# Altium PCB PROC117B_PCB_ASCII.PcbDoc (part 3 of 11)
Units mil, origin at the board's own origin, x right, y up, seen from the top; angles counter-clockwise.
Board outline 2480.32 x 3185.25 mil, 8 copper layers (Top Layer, L2_GND1, L3_SIG1, L4_PWR1, L5_PWR2, L6_SIG2, L7_GND2, Bottom Layer), stack 57.4 mil thick; 456 components, 292 nets, 7831 pads, 2905 vias.
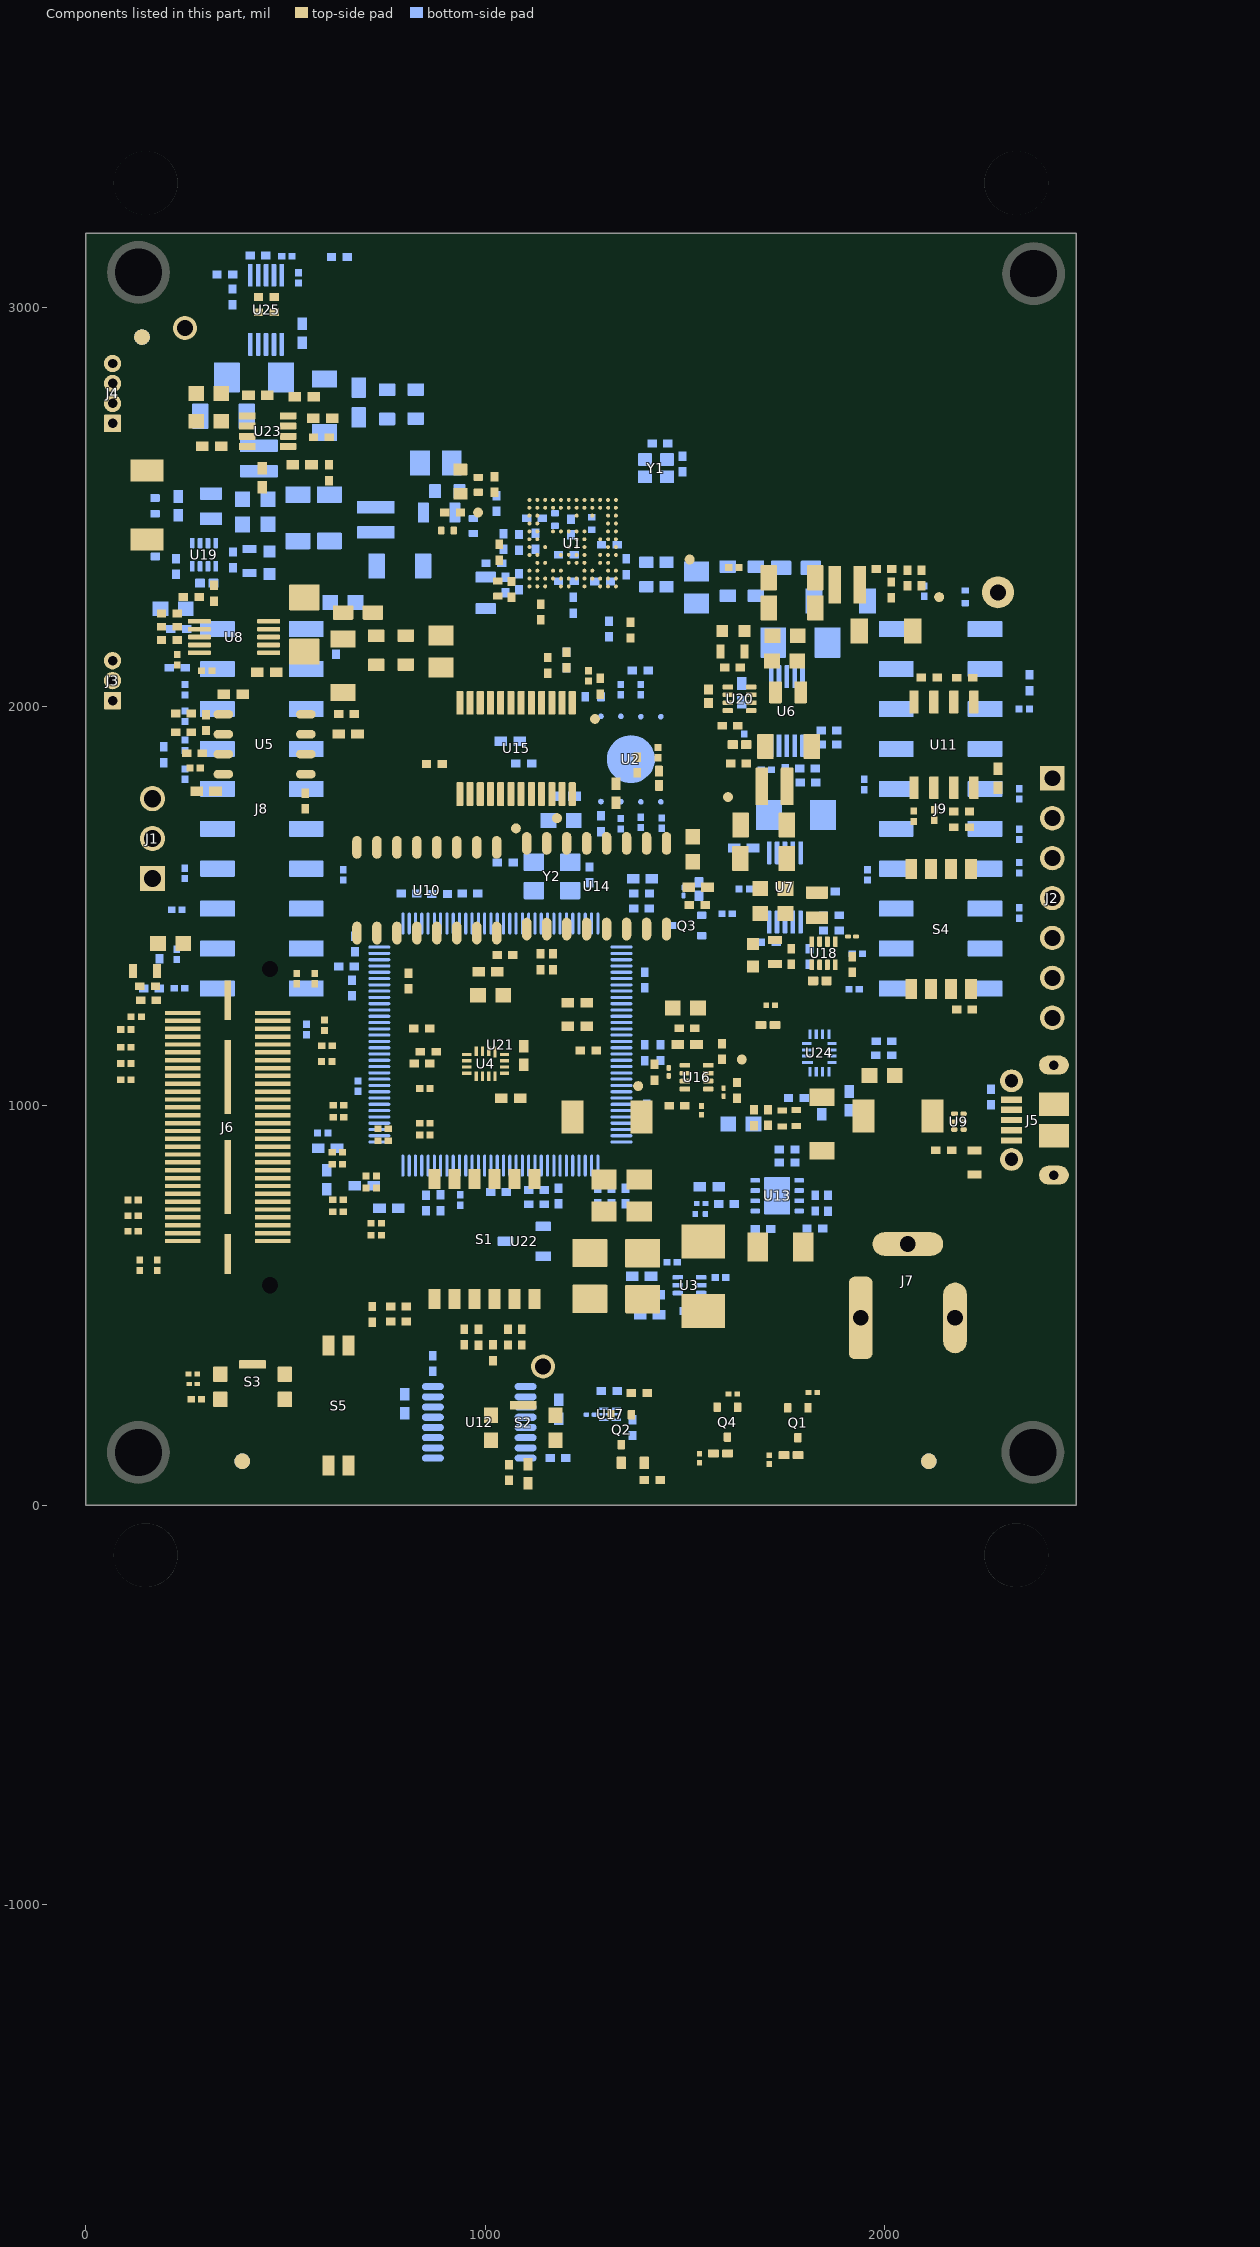
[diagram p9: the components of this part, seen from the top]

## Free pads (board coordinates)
  round 10 on Mech26: 1(22.02,-1695.57) 1(22.02,-1695.57) 1(22.02,3604.43) 1(22.02,3604.43) 1(468.93,883.94) 1(482.91,883.94) 1(1797.51,1541.73) 1(1808.94,1541.73) 1(2251.6,880.15) 1(2267.95,880.15) 1(2437.86,1526.43) 1(2449.87,1526.43) 1(2582.4,1635.88) 1(2582.4,2310.88) 1(2592.59,1635.88) 1(2592.59,2310.88) 1(2777.93,-1695.57) 1(2777.93,-1695.57) 1(2777.93,3604.43) 1(2777.93,3604.43) 1(2778.1,1386.97) 1(2778.1,1780.67) 1(2778.1,2061.97) 1(2778.1,2455.67)
  round 7.87 on Mech26: 1(58.65,440.83) 1(59.3,466.06) 1(61.75,3464.29) 1(62.4,3489.53) 1(74.37,397.26) 1(75.15,505.81) 1(77.47,3420.73) 1(78.25,3529.27) 1(86.47,382.5) 1(89.57,3405.97) 1(91.92,524.46) 1(95.02,3547.93) 1(124.31,359.12) 1(124.31,542.8) 1(127.41,3382.58) 1(127.41,3566.27) 1(140.56,546.7) 1(143.66,3570.17) 1(149.56,354.3) 1(152.65,3377.77) 1(179.56,544.58) 1(182.66,3568.05) 1(192.49,361.74) 1(194.24,539.43) 1(195.59,3385.2) 1(197.34,3562.89) 1(209.77,371.18) 1(212.87,3394.65) 1(225.87,516.84) 1(228.97,3540.3) 1(235.48,397.26) 1(238.58,3420.73) 1(238.77,499.37) 1(241.87,3522.83) 1(244.15,413.39) 1(247.25,3436.86) 1(250.55,466.06) 1(251.62,446.13) 1(253.65,3489.53) 1(254.71,3469.59) 1(318.36,412.4) 1(318.36,451.77) 1(340.88,997.43) 1(340.88,997.43) 1(340.88,1011.6) 1(340.88,1983.25) 1(340.88,1997.43) 1(340.88,1997.43) 1(349.09,597.42) 1(349.09,711.6) 1(349.09,783.25) 1(349.09,897.43) 1(349.09,897.43) 1(349.63,597.43) 1(393.17,396.66) 1(393.17,451.77) 1(449.09,886.4) 1(449.09,886.4) 1(449.09,897.43) 1(449.09,897.43) 1(449.09,897.43) 1(449.63,597.43) 1(449.63,597.43) 1(449.63,611.6) 1(489.2,886.4) 1(489.2,886.4) 1(489.2,897.43) 1(489.2,897.43) 1(492.07,503.77) 1(492.07,511.65) 1(492.07,402.4) 1(492.07,422.08) 1(540.88,997.43) 1(540.88,997.43) 1(540.88,1011.6) 1(540.88,1983.25) 1(540.88,1997.43) 1(540.88,1997.43) 1(576.72,407.32) 1(576.72,415.19) 1(576.72,503.77) 1(576.72,511.65) 1(604.49,589.05) 1(604.49,673.7) 1(611.49,739.11) 1(611.49,823.75) 1(612.36,589.05) 1(612.36,673.7) 1(619.36,739.11) 1(619.36,823.75) 1(643.79,1855.52) 1(643.79,1855.52) 1(643.79,1985.44) 1(643.79,1985.44) 1(688.23,263.16) 1(688.23,347.81) 1(692.23,444.16) 1(692.23,528.81) 1(694.06,589.05) 1(696.1,263.16) 1(696.1,347.81) 1(700.1,444.16) 1(700.1,528.81) 1(700.95,673.7) 1(701.06,739.11) 1(707.95,823.75) 1(708.82,673.7) 1(713.74,589.05) 1(715.82,823.75) 1(720.74,739.11) 1(730.41,1855.52) 1(730.41,1985.44) 1(777.8,263.16) 1(781.8,444.16) 1(784.69,347.81) 1(788.69,528.81) 1(792.56,347.81) 1(796.56,528.81) 1(797.48,263.16) 1(801.48,444.16) 1(805.99,1424.3) 1(805.99,1443.99) 1(805.99,1443.99) 1(825.36,1101.81) 1(825.36,1144.14) 1(826.38,1855.52) 1(826.38,1985.44) 1(837.49,1443.99) 1(892.61,1443.99) 1(912.99,1855.52) 1(912.99,1855.52) 1(912.99,1985.44) 1(912.99,1985.44) 1(924.1,1424.3) 1(924.1,1443.99) 1(924.1,1443.99) 1(945.44,1061.46) 1(945.44,1144.14) 1(959.94,271.75) 1(964.86,187.1) 1(972.73,187.1) 1(979.62,271.75) 1(1061.32,187.1) 1(1061.32,271.75) 1(1069.19,187.1) 1(1069.19,271.75) 1(1096.59,1330.32) 1(1096.59,1346.07) 1(1096.59,1361.81) 1(1096.59,1377.56) 1(1096.59,1393.31) 1(1096.59,1409.06) 1(1096.59,1424.81) 1(1096.59,1440.55) 1(1096.59,1456.3) 1(1096.59,1472.05) 1(1096.59,1487.8) 1(1096.59,1503.55) 1(1096.59,1519.29) 1(1096.59,1535.04) 1(1096.59,1550.79) 1(1096.59,1566.54) 1(1096.59,1582.29) 1(1096.59,1598.03) 1(1096.59,1613.78) 1(1096.59,1629.53) 1(1096.59,1645.28) 1(1096.59,1661.03) 1(1096.59,1676.77) 1(1096.59,1692.52) 1(1096.59,1708.27) 1(1096.59,1724.02) 1(1096.59,1739.77) 1(1096.59,1755.51) 1(1096.59,1771.26) 1(1096.59,1787.01) 1(1096.59,1802.76) 1(1096.59,1818.51) 1(1143.83,1330.32) 1(1143.83,1346.07) 1(1143.83,1361.81) 1(1143.83,1377.56) 1(1143.83,1393.31) 1(1143.83,1409.06) 1(1143.83,1424.81) 1(1143.83,1440.55) 1(1143.83,1456.3) 1(1143.83,1472.05) 1(1143.83,1487.8) 1(1143.83,1503.55) 1(1143.83,1519.29) 1(1143.83,1535.04) 1(1143.83,1550.79) 1(1143.83,1566.54) 1(1143.83,1582.29) 1(1143.83,1598.03) 1(1143.83,1613.78) 1(1143.83,1629.53) 1(1143.83,1645.28) 1(1143.83,1661.03) 1(1143.83,1676.77) 1(1143.83,1692.52) 1(1143.83,1708.27) 1(1143.83,1724.02) 1(1143.83,1739.77) 1(1143.83,1755.51) 1(1143.83,1771.26) 1(1143.83,1787.01) 1(1143.83,1802.76) 1(1143.83,1818.51) 1(1175.33,1326.38) 1(1175.33,1326.38) 1(1175.33,1822.44) 1(1175.33,1822.44) 1(1179.27,1247.64) 1(1179.27,1294.88) 1(1179.27,1853.94) 1(1179.27,1901.18) 1(1195.01,1247.64) 1(1195.01,1294.88) 1(1195.01,1853.94) 1(1195.01,1901.18) 1(1210.76,1247.64) 1(1210.76,1294.88) 1(1210.76,1853.94) 1(1210.76,1901.18) 1(1226.51,1247.64) 1(1226.51,1294.88) 1(1226.51,1853.94) 1(1226.51,1901.18) 1(1242.26,1247.64) 1(1242.26,1294.88) 1(1242.26,1853.94) 1(1242.26,1901.18) 1(1258.01,1247.64) 1(1258.01,1294.88) 1(1258.01,1853.94) 1(1258.01,1901.18) 1(1273.75,1247.64) 1(1273.75,1294.88) 1(1273.75,1853.94) 1(1273.75,1901.18) 1(1289.5,1247.64) 1(1289.5,1294.88) 1(1289.5,1853.94) 1(1289.5,1901.18) 1(1305.25,1247.64) 1(1305.25,1294.88) 1(1305.25,1853.94) 1(1305.25,1901.18) 1(1318.45,187.56) 1(1318.45,195.44) 1(1318.45,284.02) 1(1318.45,291.89) 1(1321,1247.64) 1(1321,1294.88) 1(1321,1853.94) 1(1321,1901.18) 1(1336.75,1247.64) 1(1336.75,1294.88) 1(1336.75,1853.94) 1(1336.75,1901.18) 1(1352.49,1247.64) 1(1352.49,1294.88) 1(1352.49,1853.94) 1(1352.49,1901.18) 1(1368.24,1247.64) 1(1368.24,1294.88) 1(1368.24,1853.94) 1(1368.24,1901.18) 1(1383.99,1247.64) 1(1383.99,1294.88) 1(1383.99,1853.94) 1(1383.99,1901.18) 1(1399.74,1247.64) 1(1399.74,1294.88) 1(1399.74,1853.94) 1(1399.74,1901.18) 1(1403.1,277.13) 1(1403.1,296.81) 1(1403.1,187.56) 1(1403.1,195.44) 1(1415.49,1247.64) 1(1415.49,1294.88) 1(1415.49,1853.94) 1(1415.49,1901.18) 1(1431.23,1247.64) 1(1431.23,1294.88) 1(1431.23,1853.94) 1(1431.23,1901.18) 1(1446.98,1247.64) 1(1446.98,1294.88) 1(1446.98,1853.94) 1(1446.98,1901.18) 1(1462.73,1247.64) 1(1462.73,1294.88) 1(1462.73,1853.94) 1(1462.73,1901.18) 1(1478.48,1247.64) 1(1478.48,1294.88) 1(1478.48,1853.94) 1(1478.48,1901.18) 1(1494.23,1247.64) 1(1494.23,1294.88) 1(1494.23,1853.94) 1(1494.23,1901.18) 1(1509.97,1247.64) 1(1509.97,1294.88) 1(1509.97,1853.94) 1(1509.97,1901.18) 1(1525.72,1247.64) 1(1525.72,1294.88) 1(1525.72,1853.94) 1(1525.72,1901.18) 1(1541.47,1247.64) 1(1541.47,1294.88) 1(1541.47,1853.94) 1(1541.47,1901.18) 1(1557.22,1247.64) 1(1557.22,1294.88) 1(1557.22,1853.94) 1(1557.22,1901.18) 1(1572.97,1247.64) 1(1572.97,1294.88) 1(1572.97,1853.94) 1(1572.97,1901.18) 1(1588.72,1247.64) 1(1588.72,1294.88) 1(1588.72,1853.94) 1(1588.72,1901.18) 1(1604.46,1247.64) 1(1604.46,1294.88) 1(1604.46,1853.94) 1(1604.46,1901.18) 1(1620.21,1247.64) 1(1620.21,1294.88) 1(1620.21,1853.94) 1(1620.21,1901.18) 1(1635.96,1247.64) 1(1635.96,1294.88) 1(1635.96,1853.94) 1(1635.96,1901.18) 1(1651.71,1247.64) 1(1651.71,1294.88) 1(1651.71,1853.94) 1(1651.71,1901.18) 1(1667.46,1247.64) 1(1667.46,1294.88) 1(1667.46,1853.94) 1(1667.46,1901.18) 1(1671.39,1326.38) 1(1671.39,1326.38) 1(1671.39,1822.44) 1(1671.39,1822.44) 1(1686.79,855.1) 1(1702.68,1012.82) 1(1702.68,1012.82) 1(1702.68,1134.87) 1(1702.68,1134.87) 1(1702.89,1330.32) 1(1702.89,1346.07) 1(1702.89,1361.81) 1(1702.89,1377.56) 1(1702.89,1393.31) 1(1702.89,1409.06) 1(1702.89,1424.81) 1(1702.89,1440.55) 1(1702.89,1456.3) 1(1702.89,1472.05) 1(1702.89,1487.8) 1(1702.89,1503.55) 1(1702.89,1519.29) 1(1702.89,1535.04) 1(1702.89,1550.79) 1(1702.89,1566.54) 1(1702.89,1582.29) 1(1702.89,1598.03) 1(1702.89,1613.78) 1(1702.89,1629.53) 1(1702.89,1645.28) 1(1702.89,1661.03) 1(1702.89,1676.77) 1(1702.89,1692.52) 1(1702.89,1708.27) 1(1702.89,1724.02) 1(1702.89,1739.77) 1(1702.89,1755.51) 1(1702.89,1771.26) 1(1702.89,1787.01) 1(1702.89,1802.76) 1(1702.89,1818.51) 1(1745.09,-281.13) 1(1750.13,1330.32) 1(1750.13,1346.07) 1(1750.13,1361.81) 1(1750.13,1377.56) 1(1750.13,1393.31) 1(1750.13,1409.06) 1(1750.13,1424.81) 1(1750.13,1440.55) 1(1750.13,1456.3) 1(1750.13,1472.05) 1(1750.13,1487.8) 1(1750.13,1503.55) 1(1750.13,1519.29) 1(1750.13,1535.04) 1(1750.13,1550.79) 1(1750.13,1566.54) 1(1750.13,1582.29) 1(1750.13,1598.03) 1(1750.13,1613.78) 1(1750.13,1629.53) 1(1750.13,1645.28) 1(1750.13,1661.03) 1(1750.13,1676.77) 1(1750.13,1692.52) 1(1750.13,1708.27) 1(1750.13,1724.02) 1(1750.13,1739.77) 1(1750.13,1755.51) 1(1750.13,1771.26) 1(1750.13,1787.01) 1(1750.13,1802.76) 1(1750.13,1818.51) 1(1755.69,977.14) 1(1785.22,228.22) 1(1785.22,228.22) 1(1785.22,256.77) 1(1785.22,430.98) 1(1785.22,440.82) 1(1785.22,440.82) 1(1795.06,440.82) 1(1813.76,228.22) 1(1813.99,-159.08) 1(1826.55,855.1) 1(1826.55,977.14) 1(1828.66,1012.82) 1(1828.66,1012.82) 1(1828.66,1134.87) 1(1828.66,1134.87) 1(1842.39,1755.98) 1(1842.39,1755.98) 1(1842.39,1833.48) 1(1842.39,1833.48) 1(1842.39,1853.48) 1(1842.39,1853.48) 1(1842.39,1933.48) 1(1842.39,1933.48) 1(1842.39,1953.48) 1(1842.39,1953.48) 1(1842.39,2030.98) 1(1842.39,2030.98) 1(1851.89,1743.48) 1(1851.89,1743.48) 1(1851.89,2043.48) 1(1851.89,2043.48) 1(1852.39,1843.48) 1(1852.39,1843.48) 1(1852.39,1943.48) 1(1852.39,1943.48) 1(1855.39,1743.48) 1(1855.39,2043.48) 1(1855.39,2043.48) 1(1884.86,-281.13) 1(1884.86,-159.08) 1(1927.39,1743.48) 1(1927.39,2043.48) 1(1927.39,2043.48) 1(1930.39,1843.48) 1(1930.39,1843.48) 1(1930.39,1943.48) 1(1930.39,1943.48) 1(1930.89,1743.48) 1(1930.89,1743.48) 1(1930.89,2043.48) 1(1930.89,2043.48) 1(1940.39,1755.98) 1(1940.39,1755.98) 1(1940.39,1833.48) 1(1940.39,1833.48) 1(1940.39,1853.48) 1(1940.39,1853.48) 1(1940.39,1933.48) 1(1940.39,1933.48) 1(1940.39,1953.48) 1(1940.39,1953.48) 1(1940.39,2030.98) 1(1940.39,2030.98) 1(1968.29,228.22) 1(1968.29,440.82) 1(1978.13,228.22) 1(1978.13,228.22) 1(1978.13,238.07) 1(1978.13,430.98) 1(1978.13,440.82) 1(1978.13,440.82) 1(2040.88,997.43) 1(2040.88,997.43) 1(2040.88,1011.6) 1(2040.88,1983.25) 1(2040.88,1997.43) 1(2040.88,1997.43) 1(2131.57,597.42) 1(2131.57,711.6) 1(2131.57,783.25) 1(2131.57,897.43) 1(2131.57,897.43) 1(2132.12,597.43) 1(2216.86,267.83) 1(2216.86,275.71) 1(2216.86,166.45) 1(2216.86,186.14) 1(2231.57,886.4) 1(2231.57,886.4) 1(2231.57,897.43) 1(2231.57,897.43) 1(2231.57,897.43) 1(2232.12,597.43) 1(2232.12,597.43) 1(2232.12,611.6) 1(2240.88,997.43) 1(2240.88,997.43) 1(2240.88,1011.6) 1(2240.88,1983.25) 1(2240.88,1997.43) 1(2240.88,1997.43) 1(2271.68,886.4) 1(2271.68,886.4) 1(2271.68,897.43) 1(2271.68,897.43) 1(2273.96,-64.54) 1(2273.96,57.51) 1(2280.06,-1279.17) 1(2280.06,-1279.17) 1(2280.06,-1192.56) 1(2280.06,-1096.59) 1(2280.06,-1009.97) 1(2280.06,-1009.97) 1(2290.75,3484.29) 1(2291.4,3509.53) 1(2298.65,440.83) 1(2299.3,466.06) 1(2301.5,171.37) 1(2301.5,179.25) 1(2301.5,267.83) 1(2301.5,275.71) 1(2306.47,3440.73) 1(2307.25,3549.27) 1(2314.37,397.26) 1(2315.15,505.81) 1(2318.57,3425.97) 1(2324.02,3567.93) 1(2326.47,382.5) 1(2331.92,524.46) 1(2344.83,-64.54) 1(2355.39,1140.98) 1(2355.39,1140.98) 1(2355.39,1218.48) 1(2355.39,1218.48) 1(2355.39,1238.48) 1(2355.39,1238.48) 1(2355.39,1318.48) 1(2355.39,1318.48) 1(2355.39,1338.48) 1(2355.39,1338.48) 1(2355.39,1415.98) 1(2355.39,1415.98) 1(2356.41,3402.58) 1(2356.41,3586.27) 1(2364.31,359.12) 1(2364.31,542.8) 1(2364.89,1128.48) 1(2364.89,1128.48) 1(2364.89,1428.48) 1(2364.89,1428.48) 1(2365.39,1228.48) 1(2365.39,1228.48) 1(2365.39,1328.48) 1(2365.39,1328.48) 1(2368.39,1128.48) 1(2368.39,1128.48) 1(2368.39,1428.48) 1(2372.66,3590.17) 1(2380.56,546.7) 1(2381.65,3397.77) 1(2389.56,354.3) 1(2409.99,-1279.17) 1(2409.99,-1279.17) 1(2409.99,-1192.56) 1(2409.99,-1096.59) 1(2409.99,-1009.97) 1(2409.99,-1009.97) 1(2411.66,3588.05) 1(2413.73,57.51) 1(2419.56,544.58) 1(2424.59,3405.2) 1(2426.34,3582.89) 1(2432.49,361.74) 1(2434.24,539.43) 1(2440.39,1128.48) 1(2440.39,1128.48) 1(2440.39,1428.48) 1(2441.87,3414.65) 1(2443.39,1228.48) 1(2443.39,1228.48) 1(2443.39,1328.48) 1(2443.39,1328.48) 1(2443.89,1128.48) 1(2443.89,1128.48) 1(2443.89,1428.48) 1(2443.89,1428.48) 1(2444.34,1554.96) 1(2449.77,371.18) 1(2453.39,1140.98) 1(2453.39,1140.98) 1(2453.39,1218.48) 1(2453.39,1218.48) 1(2453.39,1238.48) 1(2453.39,1238.48) 1(2453.39,1318.48) 1(2453.39,1318.48) 1(2453.39,1338.48) 1(2453.39,1338.48) 1(2453.39,1415.98) 1(2453.39,1415.98) 1(2456.15,1621.89) 1(2457.97,3560.3) 1(2465.87,516.84) 1(2467.58,3440.73) 1(2470.87,3542.83) 1(2471.9,1554.96) 1(2471.9,1621.89) 1(2475.48,397.26) 1(2476.25,3456.86) 1(2478.77,499.37) 1(2482.65,3509.53) 1(2483.71,3489.59) 1(2484.15,413.39) 1(2490.55,466.06) 1(2491.62,446.13)
  round 7 on Mech26: 1(117.02,-430.07) 1(117.02,-430.07) 1(117.02,-389.07) 1(117.02,-389.07) 1(117.6,-380.08) 1(117.6,-380.08) 1(117.6,-339.08) 1(117.6,-339.08) 1(117.6,-281.65) 1(117.6,-281.65) 1(117.6,-240.65) 1(117.6,-240.65) 1(117.65,-331.54) 1(117.65,-331.54) 1(117.65,-290.54) 1(117.65,-290.54) 1(118.65,-482.54) 1(118.65,-482.54) 1(118.65,-441.54) 1(118.65,-441.54) 1(134.02,1461.93) 1(134.02,1461.93) 1(134.02,1502.93) 1(134.02,1502.93) 1(134.02,1510.93) 1(134.02,1510.93) 1(134.02,1551.93) 1(134.02,1551.93) 1(134.02,1412.93) 1(134.02,1412.93) 1(134.02,1453.93) 1(134.02,1453.93) 1(140.02,-430.07) 1(140.02,-389.07) 1(140.6,-380.08) 1(140.6,-339.08) 1(140.6,-281.65) 1(140.6,-240.65) 1(140.65,-331.54) 1(140.65,-290.54) 1(141.65,-482.54) 1(141.65,-441.54) 1(157.02,1461.93) 1(157.02,1502.93) 1(157.02,1510.93) 1(157.02,1551.93) 1(157.02,1412.93) 1(157.02,1453.93) 1(190.02,-430.07) 1(190.02,-389.07) 1(190.6,-380.08) 1(190.6,-339.08) 1(190.6,-281.65) 1(190.6,-240.65) 1(190.65,-331.54) 1(190.65,-290.54) 1(191.65,-482.54) 1(191.65,-441.54) 1(207.02,1461.93) 1(207.02,1502.93) 1(207.02,1510.93) 1(207.02,1551.93) 1(207.02,1412.93) 1(207.02,1453.93) 1(213.02,-430.07) 1(213.02,-430.07) 1(213.02,-389.07) 1(213.02,-389.07) 1(213.6,-380.08) 1(213.6,-380.08) 1(213.6,-339.08) 1(213.6,-339.08) 1(213.6,-281.65) 1(213.6,-281.65) 1(213.6,-240.65) 1(213.6,-240.65) 1(213.65,-331.54) 1(213.65,-331.54) 1(213.65,-290.54) 1(213.65,-290.54) 1(214.65,-482.54) 1(214.65,-482.54) 1(214.65,-441.54) 1(214.65,-441.54) 1(230.02,1461.93) 1(230.02,1461.93) 1(230.02,1502.93) 1(230.02,1502.93) 1(230.02,1510.93) 1(230.02,1510.93) 1(230.02,1551.93) 1(230.02,1551.93) 1(230.02,1412.93) 1(230.02,1412.93) 1(230.02,1453.93) 1(230.02,1453.93) 1(335.65,-453.54) 1(335.65,-453.54) 1(335.65,-412.54) 1(335.65,-412.54) 1(336.65,-126.54) 1(336.65,-126.54) 1(336.65,-85.54) 1(336.65,-85.54) 1(336.65,-75.54) 1(336.65,-75.54) 1(336.65,-34.54) 1(336.65,-34.54) 1(337.15,-403.04) 1(337.15,-403.04) 1(337.15,-380.04) 1(337.15,-330.04) 1(337.15,-307.04) 1(337.15,-307.04) 1(337.65,26.46) 1(337.65,26.46) 1(337.65,67.46) 1(337.65,67.46) 1(337.9,-24.54) 1(337.9,-24.54) 1(337.9,16.46) 1(337.9,16.46) 1(338.65,77.46) 1(338.65,77.46) 1(338.65,118.46) 1(338.65,118.46) 1(358.65,-453.54) 1(358.65,-412.54) 1(359.65,-126.54) 1(359.65,-85.54) 1(359.65,-75.54) 1(359.65,-34.54) 1(360.65,26.46) 1(360.65,67.46) 1(360.9,-24.54) 1(360.9,16.46) 1(361.65,77.46) 1(361.65,118.46) 1(378.15,-403.04) 1(378.15,-403.04) 1(378.15,-380.04) 1(378.15,-330.04) 1(378.15,-307.04) 1(378.15,-307.04) 1(388.15,-403.04) 1(388.15,-403.04) 1(388.15,-380.04) 1(388.15,-330.04) 1(388.15,-307.04) 1(388.15,-307.04) 1(408.65,-453.54) 1(408.65,-412.54) 1(409.65,-126.54) 1(409.65,-85.54) 1(409.65,-75.54) 1(409.65,-34.54) 1(410.65,26.46) 1(410.65,67.46) 1(410.9,-24.54) 1(410.9,16.46) 1(411.65,77.46) 1(411.65,118.46) 1(429.15,-403.04) 1(429.15,-403.04) 1(429.15,-380.04) 1(429.15,-330.04) 1(429.15,-307.04) 1(429.15,-307.04) 1(431.65,-453.54) 1(431.65,-453.54) 1(431.65,-412.54) 1(431.65,-412.54) 1(432.65,-126.54) 1(432.65,-126.54) 1(432.65,-85.54) 1(432.65,-85.54) 1(432.65,-75.54) 1(432.65,-75.54) 1(432.65,-34.54) 1(432.65,-34.54) 1(433.65,26.46) 1(433.65,26.46) 1(433.65,67.46) 1(433.65,67.46) 1(433.9,-24.54) 1(433.9,-24.54) 1(433.9,16.46) 1(433.9,16.46) 1(434.65,77.46) 1(434.65,77.46) 1(434.65,118.46) 1(434.65,118.46) 1(493.76,-42.01) 1(493.76,-42.01) 1(493.76,-6.57) 1(493.76,111.54) 1(493.76,146.97) 1(493.76,146.97) 1(531.16,2733.99) 1(531.16,2733.99) 1(531.16,2769.43) 1(531.16,2887.54) 1(531.16,2922.97) 1(531.16,2922.97) 1(538.73,-811.85) 1(538.73,-811.85) 1(538.73,-770.85) 1(538.73,-770.85) 1(538.73,-735.98) 1(538.73,-735.98) 1(538.73,-694.98) 1(538.73,-694.98) 1(538.91,-554.15) 1(538.91,-554.15) 1(538.91,-458.88) 1(538.91,-458.88) 1(540.89,158.48) 1(540.89,158.48) 1(540.89,181.48) 1(540.89,231.48) 1(540.89,254.48) 1(540.89,254.48) 1(561.73,-811.85) 1(561.73,-770.85) 1(561.73,-735.98) 1(561.73,-694.98) 1(563.76,-686.55) 1(563.76,-686.55) 1(563.76,-660.57) 1(563.76,-592.57) 1(563.76,-566.59) 1(563.76,-566.59) 1(568.52,-970.57) 1(568.52,-970.57) 1(568.52,-947.57) 1(568.52,-897.57) 1(568.52,-874.57) 1(568.52,-874.57) 1(574.34,-554.15) 1(574.34,-458.88) 1(581.89,158.48) 1(581.89,158.48) 1(581.89,181.48) 1(581.89,231.48) 1(581.89,254.48) 1(581.89,254.48) 1(589.03,-42.01) 1(589.03,-42.01) 1(589.03,-6.57) 1(589.03,111.54) 1(589.03,146.97) 1(589.03,146.97) 1(609.52,-970.57) 1(609.52,-970.57) 1(609.52,-947.57) 1(609.52,-897.57) 1(609.52,-874.57) 1(609.52,-874.57) 1(611.73,-811.85) 1(611.73,-770.85) 1(611.73,-735.98) 1(611.73,-694.98) 1(618.22,-686.55) 1(618.22,-686.55) 1(618.22,-660.57) 1(618.22,-592.57) 1(618.22,-566.59) 1(618.22,-566.59) 1(618.52,-970.57) 1(618.52,-970.57) 1(618.52,-947.57) 1(618.52,-897.57) 1(618.52,-874.57) 1(618.52,-874.57) 1(626.44,2733.99) 1(626.44,2733.99) 1(626.44,2769.43) 1(626.44,2887.54) 1(626.44,2922.97) 1(626.44,2922.97) 1(634.73,-811.85) 1(634.73,-811.85) 1(634.73,-770.85) 1(634.73,-770.85) 1(634.73,-735.98) 1(634.73,-735.98) 1(634.73,-694.98) 1(634.73,-694.98) 1(659.52,-970.57) 1(659.52,-970.57) 1(659.52,-947.57) 1(659.52,-897.57) 1(659.52,-874.57) 1(659.52,-874.57) 1(664.65,-619.54) 1(664.65,-619.54) 1(664.65,-578.54) 1(664.65,-578.54) 1(668.4,-805.07) 1(668.4,-805.07) 1(668.4,-764.07) 1(668.4,-764.07) 1(669.71,-971.92) 1(669.71,-971.92) 1(669.71,-948.92) 1(669.71,-898.92) 1(669.71,-875.92) 1(669.71,-875.92) 1(673.4,-715.07) 1(673.4,-715.07) 1(673.4,-674.07) 1(673.4,-674.07) 1(687.65,-619.54) 1(687.65,-578.54) 1(691.4,-805.07) 1(691.4,-764.07) 1(692.45,-554.15) 1(692.45,-458.88) 1(696.4,-715.07) 1(696.4,-674.07) 1(710.71,-971.92) 1(710.71,-971.92) 1(710.71,-948.92) 1(710.71,-898.92) 1(710.71,-875.92) 1(710.71,-875.92) 1(712.02,98.98) 1(712.02,98.98) 1(712.02,139.98) 1(712.02,139.98) 1(721.39,-191.02) 1(721.39,-191.02) 1(721.39,-150.02) 1(721.39,-150.02) 1(722.39,-17.02) 1(722.39,-17.02) 1(722.39,23.98) 1(722.39,23.98) 1(722.77,-108.02) 1(722.77,-108.02) 1(722.77,-67.02) 1(722.77,-67.02) 1(724.71,-971.92) 1(724.71,-971.92) 1(724.71,-948.92) 1(724.71,-898.92) 1(724.71,-875.92) 1(724.71,-875.92) 1(727.88,-554.15) 1(727.88,-554.15) 1(727.88,-458.88) 1(727.88,-458.88) 1(735.02,98.98) 1(735.02,139.98) 1(737.65,-619.54) 1(737.65,-578.54) 1(741.4,-805.07) 1(741.4,-764.07) 1(744.39,-191.02) 1(744.39,-150.02) 1(745.39,-17.02) 1(745.39,23.98) 1(745.76,1525.99) 1(745.76,1525.99) 1(745.76,1561.43) 1(745.76,1679.54) 1(745.76,1714.97) 1(745.76,1714.97) 1(745.77,-108.02) 1(745.77,-67.02) 1(746.4,-715.07) 1(746.4,-674.07) 1(757.65,807.93) 1(757.65,807.93) 1(757.65,848.93) 1(757.65,848.93) 1(760.65,-619.54) 1(760.65,-619.54) 1(760.65,-578.54) 1(760.65,-578.54) 1(764.02,2707.27) 1(764.02,2707.27) 1(764.02,2748.27) 1(764.02,2748.27) 1(764.02,2757.27) 1(764.02,2757.27) 1(764.02,2798.27) 1(764.02,2798.27) 1(764.02,2857.27) 1(764.02,2857.27) 1(764.02,2898.27) 1(764.02,2898.27) 1(764.02,2807.27) 1(764.02,2807.27) 1(764.02,2848.27) 1(764.02,2848.27) 1(764.4,-805.07) 1(764.4,-805.07) 1(764.4,-764.07) 1(764.4,-764.07) 1(765.71,-971.92) 1(765.71,-971.92) 1(765.71,-948.92) 1(765.71,-898.92) 1(765.71,-875.92) 1(765.71,-875.92) 1(769.4,-715.07) 1(769.4,-715.07) 1(769.4,-674.07) 1(769.4,-674.07) 1(780.65,807.93) 1(780.65,848.93) 1(782.28,683.87) 1(782.28,683.87) 1(782.28,724.87) 1(782.28,724.87) 1(785.02,98.98) 1(785.02,139.98) 1(787.02,2707.27) 1(787.02,2748.27) 1(787.02,2757.27) 1(787.02,2798.27) 1(787.02,2857.27) 1(787.02,2898.27) 1(787.02,2807.27) 1(787.02,2848.27) 1(790.89,-974.52) 1(790.89,-974.52) 1(790.89,-951.52) 1(790.89,-901.52) 1(790.89,-878.52) 1(790.89,-878.52) 1(794.39,-191.02) 1(794.39,-150.02) 1(795.39,-17.02) 1(795.39,23.98) 1(795.77,-108.02) 1(795.77,-67.02) 1(805.28,683.87) 1(805.28,724.87) 1(808.02,98.98) 1(808.02,98.98) 1(808.02,139.98) 1(808.02,139.98) 1(808.63,1236.03) 1(808.63,1309.03) 1(808.63,1309.03) 1(808.63,1213.03) 1(808.63,1213.03) 1(808.63,1286.03) 1(817.39,-191.02) 1(817.39,-191.02) 1(817.39,-150.02) 1(817.39,-150.02) 1(818.39,-17.02) 1(818.39,-17.02) 1(818.39,23.98) 1(818.39,23.98) 1(818.77,-108.02) 1(818.77,-108.02) 1(818.77,-67.02) 1(818.77,-67.02) 1(821.52,931.43) 1(821.52,931.43) 1(821.52,954.43) 1(821.52,1004.43) 1(821.52,1027.43) 1(821.52,1027.43) 1(823.77,173.98) 1(823.77,173.98) 1(823.77,214.98) 1(823.77,214.98) 1(830.65,807.93) 1(830.65,848.93) 1(831.89,-974.52) 1(831.89,-974.52) 1(831.89,-951.52) 1(831.89,-901.52) 1(831.89,-878.52) 1(831.89,-878.52) 1(837.02,2707.27) 1(837.02,2748.27) 1(837.02,2757.27) 1(837.02,2798.27) 1(837.02,2857.27) 1(837.02,2898.27) 1(837.02,2807.27) 1(837.02,2848.27) 1(841.03,1525.99) 1(841.03,1525.99) 1(841.03,1561.43) 1(841.03,1679.54) 1(841.03,1714.97) 1(841.03,1714.97) 1(846.77,173.98) 1(846.77,214.98) 1(849.63,1213.03) 1(849.63,1213.03) 1(849.63,1286.03) 1(849.63,1236.03) 1(849.63,1309.03) 1(849.63,1309.03) 1(850.89,-974.52) 1(850.89,-974.52) 1(850.89,-951.52) 1(850.89,-901.52) 1(850.89,-878.52) 1(850.89,-878.52) 1(853.65,807.93) 1(853.65,807.93) 1(853.65,848.93) 1(853.65,848.93) 1(855.28,683.87) 1(855.28,724.87) 1(857.62,1213.23) 1(857.62,1213.23) 1(857.62,1236.23) 1(857.62,1286.23) 1(857.62,1309.23) 1(857.62,1309.23) 1(860.02,2707.27) 1(860.02,2707.27) 1(860.02,2748.27) 1(860.02,2748.27) 1(860.02,2757.27) 1(860.02,2757.27) 1(860.02,2798.27) 1(860.02,2798.27) 1(860.02,2857.27) 1(860.02,2857.27) 1(860.02,2898.27) 1(860.02,2898.27) 1(860.02,2807.27) 1(860.02,2807.27) 1(860.02,2848.27) 1(860.02,2848.27) 1(862.52,931.43) 1(862.52,931.43) 1(862.52,954.43) 1(862.52,1004.43) 1(862.52,1027.43) 1(862.52,1027.43) 1(878.28,683.87) 1(878.28,683.87) 1(878.28,724.87) 1(878.28,724.87) 1(887.39,121.98) 1(887.39,121.98) 1(887.39,162.98) 1(887.39,162.98) 1(891.89,-974.52) 1(891.89,-974.52) 1(891.89,-951.52) 1(891.89,-901.52) 1(891.89,-878.52) 1(891.89,-878.52) 1(895.13,911.24) 1(895.13,911.24) 1(895.13,937.22) 1(895.13,1005.22) 1(895.13,1031.21) 1(895.13,1031.21) 1(896.77,173.98) 1(896.77,214.98) 1(898.62,1213.23) 1(898.62,1213.23) 1(898.62,1236.23) 1(898.62,1286.23) 1(898.62,1309.23) 1(898.62,1309.23) 1(907.19,1209.44) 1(907.19,1209.44) 1(907.19,1235.43) 1(907.19,1303.43) 1(907.19,1329.41) 1(907.19,1329.41) 1(910.39,121.98) 1(910.39,162.98) 1(919.77,173.98) 1(919.77,173.98) 1(919.77,214.98) 1(919.77,214.98) 1(949.59,911.24) 1(949.59,911.24) 1(949.59,937.22) 1(949.59,1005.22) 1(949.59,1031.21) 1(949.59,1031.21) 1(950.39,1682.98) 1(950.39,1682.98) 1(950.39,1723.98) 1(950.39,1723.98) 1(950.88,1583.08) 1(950.88,1583.08) 1(950.88,1624.08) 1(950.88,1624.08) 1(950.89,-970.89) 1(950.89,-970.89) 1(950.89,-947.89) 1(950.89,-897.89) 1(950.89,-874.89) 1(950.89,-874.89) 1(951.39,1632.98) 1(951.39,1632.98) 1(951.39,1673.98) 1(951.39,1673.98) 1(960.39,121.98) 1(960.39,162.98) 1(961.66,1209.44) 1(961.66,1209.44) 1(961.66,1235.43) 1(961.66,1303.43) 1(961.66,1329.41) 1(961.66,1329.41) 1(973.39,1682.98) 1(973.39,1723.98) 1(973.88,1583.08) 1(973.88,1624.08) 1(974.39,1632.98) 1(974.39,1673.98) 1(983.39,121.98) 1(983.39,121.98) 1(983.39,162.98) 1(983.39,162.98) 1(987.13,-55.5) 1(987.13,-55.5) 1(987.13,-29.52) 1(987.13,38.48) 1(987.13,64.47) 1(987.13,64.47) 1(991.89,-970.89) 1(991.89,-970.89) 1(991.89,-947.89) 1(991.89,-897.89) 1(991.89,-874.89) 1(991.89,-874.89) 1(1005.89,-970.89) 1(1005.89,-970.89) 1(1005.89,-947.89) 1(1005.89,-897.89) 1(1005.89,-874.89) 1(1005.89,-874.89) 1(1023.39,1682.98) 1(1023.39,1723.98) 1(1023.88,1583.08) 1(1023.88,1624.08) 1(1024.39,1632.98) 1(1024.39,1673.98) 1(1041.59,-55.5) 1(1041.59,-55.5) 1(1041.59,-29.52) 1(1041.59,38.48) 1(1041.59,64.47) 1(1041.59,64.47) 1(1042.39,1906.98) 1(1042.39,1906.98) 1(1042.39,1947.98) 1(1042.39,1947.98) 1(1042.39,1956.98) 1(1042.39,1956.98) 1(1042.39,1997.98) 1(1042.39,1997.98) 1(1046.39,1682.98) 1(1046.39,1682.98) 1(1046.39,1723.98) 1(1046.39,1723.98) 1(1046.88,1583.08) 1(1046.88,1583.08) 1(1046.88,1624.08) 1(1046.88,1624.08) 1(1046.89,-970.89) 1(1046.89,-970.89) 1(1046.89,-947.89) 1(1046.89,-897.89) 1(1046.89,-874.89) 1(1046.89,-874.89) 1(1047.39,1632.98) 1(1047.39,1632.98) 1(1047.39,1673.98) 1(1047.39,1673.98) 1(1058.67,-971.92) 1(1058.67,-971.92) 1(1058.67,-948.92) 1(1058.67,-898.92) 1(1058.67,-875.92) 1(1058.67,-875.92) 1(1065.39,1906.98) 1(1065.39,1947.98) 1(1065.39,1956.98) 1(1065.39,1997.98) 1(1069.17,43.14) 1(1069.17,43.14) 1(1069.17,97.6) 1(1069.17,97.6) 1(1095.15,43.14) 1(1095.15,97.6) 1(1099.67,-971.92) 1(1099.67,-971.92) 1(1099.67,-948.92) 1(1099.67,-898.92) 1(1099.67,-875.92) 1(1099.67,-875.92) 1(1115.39,1906.98) 1(1115.39,1947.98) 1(1115.39,1956.98) 1(1115.39,1997.98) 1(1119.39,-824.02) 1(1119.39,-824.02) 1(1119.39,-783.02) 1(1119.39,-783.02) 1(1138.39,1906.98) 1(1138.39,1906.98) 1(1138.39,1947.98) 1(1138.39,1947.98) 1(1138.39,1956.98) 1(1138.39,1956.98) 1(1138.39,1997.98) 1(1138.39,1997.98) 1(1140.39,-979.22) 1(1140.39,-979.22) 1(1140.39,-938.22) 1(1140.39,-938.22) 1(1140.39,-929.02) 1(1140.39,-929.02) 1(1140.39,-888.02) 1(1140.39,-888.02) 1(1142.39,-824.02) 1(1142.39,-783.02) 1(1158.77,1052.98) 1(1158.77,1052.98) 1(1158.77,1093.98) 1(1158.77,1093.98) 1(1163.15,43.14) 1(1163.15,97.6) 1(1163.39,-979.22) 1(1163.39,-938.22) 1(1163.39,-929.02) 1(1163.39,-888.02) 1(1175.77,250.98) 1(1175.77,250.98) 1(1175.77,291.98) 1(1175.77,291.98) 1(1181.77,1052.98) 1(1181.77,1093.98) 1(1189.13,43.14) 1(1189.13,43.14) 1(1189.13,97.6) 1(1189.13,97.6) 1(1192.39,-824.02) 1(1192.39,-783.02) 1(1198.77,250.98) 1(1198.77,291.98) 1(1212.01,1948.81) 1(1212.01,1948.81) 1(1212.01,1971.81) 1(1212.01,2021.81) 1(1212.01,2044.81) 1(1212.01,2044.81) 1(1213.39,-979.22) 1(1213.39,-938.22) 1(1213.39,-929.02) 1(1213.39,-888.02) 1(1215.39,-824.02) 1(1215.39,-824.02) 1(1215.39,-783.02) 1(1215.39,-783.02) 1(1221.52,877.81) 1(1221.52,877.81) 1(1221.52,900.81) 1(1221.52,950.81) 1(1221.52,973.81) 1(1221.52,973.81) 1(1231.77,1052.98) 1(1231.77,1093.98) 1(1236.39,-979.22) 1(1236.39,-979.22) 1(1236.39,-938.22) 1(1236.39,-938.22) 1(1236.39,-929.02) 1(1236.39,-929.02) 1(1236.39,-888.02) 1(1236.39,-888.02) 1(1240.84,-172.29) 1(1240.84,-172.29) 1(1240.84,-131.29) 1(1240.84,-131.29) 1(1248.34,-119.79) 1(1248.34,-119.79) 1(1248.34,-96.79) 1(1248.34,-46.79) 1(1248.34,-23.79) 1(1248.34,-23.79) 1(1248.77,250.98) 1(1248.77,291.98) 1(1253.01,1948.81) 1(1253.01,1948.81) 1(1253.01,1971.81) 1(1253.01,2021.81) 1(1253.01,2044.81) 1(1253.01,2044.81) 1(1254.77,1052.98) 1(1254.77,1052.98) 1(1254.77,1093.98) 1(1254.77,1093.98) 1(1255.39,337.98) 1(1255.39,337.98) 1(1255.39,378.98) 1(1255.39,378.98) 1(1262.52,877.81) 1(1262.52,877.81) 1(1262.52,900.81) 1(1262.52,950.81) 1(1262.52,973.81) 1(1262.52,973.81) 1(1263.84,-172.29) 1(1263.84,-131.29) 1(1271.77,250.98) 1(1271.77,250.98) 1(1271.77,291.98) 1(1271.77,291.98) 1(1277.04,907.62) 1(1277.04,907.62) 1(1277.04,930.62) 1(1277.04,980.62) 1(1277.04,1003.62) 1(1277.04,1003.62) 1(1277.04,1012.62) 1(1277.04,1012.62) 1(1277.04,1035.62) 1(1277.04,1085.62) 1(1277.04,1108.62) 1(1277.04,1108.62) 1(1278.39,337.98) 1(1278.39,378.98) 1(1279.02,-979.22) 1(1279.02,-979.22) 1(1279.02,-938.22) 1(1279.02,-938.22) 1(1284.39,701.98) 1(1284.39,701.98) 1(1284.39,742.98) 1(1284.39,742.98) 1(1289.34,-119.79) 1(1289.34,-119.79) 1(1289.34,-96.79) 1(1289.34,-46.79) 1(1289.34,-23.79) 1(1289.34,-23.79) 1(1302.02,-979.22) 1(1302.02,-938.22) 1(1303.34,-119.79) 1(1303.34,-119.79) 1(1303.34,-96.79) 1(1303.34,-46.79) 1(1303.34,-23.79) 1(1303.34,-23.79) 1(1307.39,701.98) 1(1307.39,742.98) 1(1313.84,-172.29) 1(1313.84,-131.29) 1(1317.81,-932.02) 1(1317.81,-932.02) 1(1317.81,-891.02) 1(1317.81,-891.02) 1(1318.04,907.62) 1(1318.04,907.62) 1(1318.04,930.62) 1(1318.04,980.62) 1(1318.04,1003.62) 1(1318.04,1003.62) 1(1318.04,1012.62) 1(1318.04,1012.62) 1(1318.04,1035.62) 1(1318.04,1085.62) 1(1318.04,1108.62) 1(1318.04,1108.62) 1(1328.39,337.98) 1(1328.39,378.98) 1(1334.02,503.93) 1(1334.02,503.93) 1(1334.02,544.93) 1(1334.02,544.93) 1(1334.02,568.93) 1(1334.02,568.93) 1(1334.02,609.93) 1(1334.02,609.93) 1(1336.84,-172.29) 1(1336.84,-172.29) 1(1336.84,-131.29) 1(1336.84,-131.29) 1(1340.81,-932.02) 1(1340.81,-891.02) 1(1341.38,1926.01) 1(1341.38,1926.01) 1(1341.38,1949.01) 1(1341.38,1999.01) 1(1341.38,2022.01) 1(1341.38,2022.01) 1(1344.34,-119.79) 1(1344.34,-119.79) 1(1344.34,-96.79) 1(1344.34,-46.79) 1(1344.34,-23.79) 1(1344.34,-23.79) 1(1351.39,337.98) 1(1351.39,337.98) 1(1351.39,378.98) 1(1351.39,378.98) 1(1352.02,-979.22) 1(1352.02,-938.22) 1(1357.02,503.93) 1(1357.02,544.93) 1(1357.02,568.93) 1(1357.02,609.93) 1(1357.39,701.98) 1(1357.39,742.98) 1(1375.02,-979.22) 1(1375.02,-979.22) 1(1375.02,-938.22) 1(1375.02,-938.22) 1(1380.39,701.98) 1(1380.39,701.98) 1(1380.39,742.98) 1(1380.39,742.98) 1(1382.38,1926.01) 1(1382.38,1926.01) 1(1382.38,1949.01) 1(1382.38,1999.01) 1(1382.38,2022.01) 1(1382.38,2022.01) 1(1390.81,-932.02) 1(1390.81,-891.02) 1(1392.98,-981.25) 1(1392.98,-981.25) 1(1392.98,-940.25) 1(1392.98,-940.25) 1(1401.52,907.62) 1(1401.52,907.62) 1(1401.52,930.62) 1(1401.52,980.62) 1(1401.52,1003.62) 1(1401.52,1003.62) 1(1401.8,1012.62) 1(1401.8,1012.62) 1(1401.8,1035.62) 1(1401.8,1085.62) 1(1401.8,1108.62) 1(1401.8,1108.62) 1(1407.02,503.93) 1(1407.02,544.93) 1(1407.02,568.93) 1(1407.02,609.93) 1(1413.81,-932.02) 1(1413.81,-932.02) 1(1413.81,-891.02) 1(1413.81,-891.02) 1(1415.98,-981.25) 1(1415.98,-940.25) 1(1422.89,1116.48) 1(1422.89,1116.48) 1(1422.89,1139.48) 1(1422.89,1189.48) 1(1422.89,1212.48) 1(1422.89,1212.48) 1(1424.02,340.93) 1(1424.02,340.93) 1(1424.02,381.93) 1(1424.02,381.93) 1(1429.62,414.17) 1(1429.62,414.17) 1(1429.62,455.17) 1(1429.62,455.17) 1(1430.02,503.93) 1(1430.02,503.93) 1(1430.02,544.93) 1(1430.02,544.93) 1(1430.02,568.93) 1(1430.02,568.93) 1(1430.02,609.93) 1(1430.02,609.93) 1(1431.29,-214.95) 1(1431.29,-214.95) 1(1431.29,-173.95) 1(1431.29,-173.95) 1(1432.19,-116.8) 1(1432.19,-116.8) 1(1432.19,-75.8) 1(1432.19,-75.8) 1(1432.19,-66.8) 1(1432.19,-66.8) 1(1432.19,-25.8) 1(1432.19,-25.8) 1(1432.19,-166.8) 1(1432.19,-166.8) 1(1432.19,-125.8) 1(1432.19,-125.8) 1(1432.19,-16.8) 1(1432.19,-16.8) 1(1432.19,24.2) 1(1432.19,24.2) 1(1442.52,907.62) 1(1442.52,907.62) 1(1442.52,930.62) 1(1442.52,980.62) 1(1442.52,1003.62) 1(1442.52,1003.62) 1(1442.8,1012.62) 1(1442.8,1012.62) 1(1442.8,1035.62) 1(1442.8,1085.62) 1(1442.8,1108.62) 1(1442.8,1108.62) 1(1447.02,340.93) 1(1447.02,381.93) 1(1452.62,414.17) 1(1452.62,455.17) 1(1454.29,-214.95) 1(1454.29,-173.95) 1(1455.19,-116.8) 1(1455.19,-75.8) 1(1455.19,-66.8) 1(1455.19,-25.8) 1(1455.19,-166.8) 1(1455.19,-125.8) 1(1455.19,-16.8) 1(1455.19,24.2) 1(1463.89,1116.48) 1(1463.89,1116.48) 1(1463.89,1139.48) 1(1463.89,1189.48) 1(1463.89,1212.48) 1(1463.89,1212.48) 1(1465.98,-981.25) 1(1465.98,-940.25) 1(1473.39,1158.98) 1(1473.39,1158.98) 1(1473.39,1199.98) 1(1473.39,1199.98) 1(1488.98,-981.25) 1(1488.98,-981.25) 1(1488.98,-940.25) 1(1488.98,-940.25) 1(1493.95,883.8) 1(1493.95,883.8) 1(1493.95,924.8) 1(1493.95,924.8) 1(1494.06,817.06) 1(1494.06,817.06) 1(1494.06,858.06) 1(1494.06,858.06) 1(1496.39,1158.98) 1(1496.39,1199.98) 1(1497.02,340.93) 1(1497.02,381.93) 1(1502.62,414.17) 1(1502.62,455.17) 1(1504.29,-214.95) 1(1504.29,-173.95) 1(1505.19,-116.8) 1(1505.19,-75.8) 1(1505.19,-66.8) 1(1505.19,-25.8) 1(1505.19,-166.8) 1(1505.19,-125.8) 1(1505.19,-16.8) 1(1505.19,24.2) 1(1516.95,883.8) 1(1516.95,924.8) 1(1517.06,817.06) 1(1517.06,858.06) 1(1520.02,340.93) 1(1520.02,340.93) 1(1520.02,381.93) 1(1520.02,381.93) 1(1525.62,414.17) 1(1525.62,414.17) 1(1525.62,455.17) 1(1525.62,455.17) 1(1527.29,-214.95) 1(1527.29,-214.95) 1(1527.29,-173.95) 1(1527.29,-173.95) 1(1528.19,-116.8) 1(1528.19,-116.8) 1(1528.19,-75.8) 1(1528.19,-75.8) 1(1528.19,-66.8) 1(1528.19,-66.8) 1(1528.19,-25.8) 1(1528.19,-25.8) 1(1528.19,-166.8) 1(1528.19,-166.8) 1(1528.19,-125.8) 1(1528.19,-125.8) 1(1528.19,-16.8) 1(1528.19,-16.8) 1(1528.19,24.2) 1(1528.19,24.2) 1(1531.87,-987.02) 1(1531.87,-987.02) 1(1531.87,-946.02) 1(1531.87,-946.02) 1(1538.34,-114.79) 1(1538.34,-114.79) 1(1538.34,-91.79) 1(1538.34,-41.79) 1(1538.34,-18.79) 1(1538.34,-18.79) 1(1546.39,1158.98) 1(1546.39,1199.98) 1(1554.87,-987.02) 1(1554.87,-946.02) 1(1566.95,883.8) 1(1566.95,924.8) 1(1567.06,817.06) 1(1567.06,858.06) 1(1569.39,1158.98) 1(1569.39,1158.98) 1(1569.39,1199.98) 1(1569.39,1199.98) 1(1579.34,-114.79) 1(1579.34,-114.79) 1(1579.34,-91.79) 1(1579.34,-41.79) 1(1579.34,-18.79) 1(1579.34,-18.79) 1(1588.8,700.59) 1(1588.8,700.59) 1(1588.8,795.86) 1(1588.8,795.86) 1(1589.95,883.8) 1(1589.95,883.8) 1(1589.95,924.8) 1(1589.95,924.8) 1(1590.06,817.06) 1(1590.06,817.06) 1(1590.06,858.06) 1(1590.06,858.06) 1(1599.62,-137.11) 1(1599.62,-137.11) 1(1599.62,-41.84) 1(1599.62,-41.84) 1(1604.87,-987.02) 1(1604.87,-946.02) 1(1624.24,700.59) 1(1624.24,795.86) 1(1627.87,-987.02) 1(1627.87,-987.02) 1(1627.87,-946.02) 1(1627.87,-946.02) 1(1635.05,-137.11) 1(1635.05,-41.84) 1(1665.65,2729.92) 1(1665.65,2729.92) 1(1665.65,2770.92) 1(1665.65,2770.92) 1(1665.65,2788.93) 1(1665.65,2788.93) 1(1665.65,2829.93) 1(1665.65,2829.93) 1(1688.65,2729.92) 1(1688.65,2770.92) 1(1688.65,2788.93) 1(1688.65,2829.93) 1(1693.03,2942.92) 1(1693.03,2942.92) 1(1693.03,2983.92) 1(1693.03,2983.92) 1(1694.03,2996.92) 1(1694.03,2996.92) 1(1694.03,3037.92) 1(1694.03,3037.92) 1(1694.65,2624.93) 1(1694.65,2624.93) 1(1694.65,2665.93) 1(1694.65,2665.93) 1(1716.03,2942.92) 1(1716.03,2983.92) 1(1716.77,2678.8) 1(1716.77,2678.8) 1(1716.77,2701.8) 1(1716.77,2774.8) 1(1716.78,2785.05) 1(1716.78,2858.05) 1(1716.78,2881.05) 1(1716.78,2881.05) 1(1717.03,2996.92) 1(1717.03,3037.92) 1(1717.65,2624.93) 1(1717.65,2665.93) 1(1733.24,95.75) 1(1733.24,95.75) 1(1733.24,135.75) 1(1733.24,135.75) 1(1733.24,175.75) 1(1733.24,175.75) 1(1733.24,491.89) 1(1733.24,491.89) 1(1733.24,531.89) 1(1733.24,531.89) 1(1733.24,571.89) 1(1733.24,571.89) 1(1742.35,795.86) 1(1744.15,2891.8) 1(1744.15,2891.8) 1(1744.15,2914.8) 1(1744.15,2987.8) 1(1744.78,2572.81) 1(1744.78,2572.81) 1(1744.78,2595.81) 1(1744.78,2668.81) 1(1753.17,-137.11) 1(1753.17,-41.84) 1(1757.77,2678.8) 1(1757.77,2678.8) 1(1757.77,2701.8) 1(1757.77,2774.8) 1(1757.78,2785.05) 1(1757.78,2858.05) 1(1757.78,2881.05) 1(1757.78,2881.05) 1(1761.65,2729.92) 1(1761.65,2770.92) 1(1761.65,2788.93) 1(1761.65,2829.93) 1(1767.03,2996.92) 1(1767.03,3037.92) 1(1767.24,95.75) 1(1767.24,175.75) 1(1767.24,491.89) 1(1767.24,571.89) 1(1777.51,-996.27) 1(1777.51,-996.27) 1(1777.51,-955.27) 1(1777.51,-955.27) 1(1777.78,709.59) 1(1777.78,795.86) 1(1777.78,795.86) 1(1785.15,2891.8) 1(1785.15,2891.8) 1(1785.15,2914.8) 1(1785.15,2987.8) 1(1785.78,2572.81) 1(1785.78,2572.81) 1(1785.78,2595.81) 1(1785.78,2668.81) 1(1788.6,-137.11) 1(1788.6,-137.11) 1(1788.6,-41.84) 1(1788.6,-41.84) 1(1789.03,2942.92) 1(1789.03,2983.92) 1(1790.03,2996.92) 1(1790.03,2996.92) 1(1790.03,3037.92) 1(1790.03,3037.92) 1(1790.65,2624.93) 1(1790.65,2665.93) 1(1800.51,-996.27) 1(1800.51,-955.27) 1(1847.24,95.75) 1(1847.24,175.75) 1(1847.24,491.89) 1(1847.24,571.89) 1(1850.51,-996.27) 1(1850.51,-955.27) 1(1873.51,-996.27) 1(1873.51,-996.27) 1(1873.51,-955.27) 1(1873.51,-955.27) 1(1879.24,491.89) 1(1879.24,491.89) 1(1879.24,531.89) 1(1879.24,531.89) 1(1879.24,571.89) 1(1879.24,571.89) 1(1881.24,95.75) 1(1881.24,95.75) 1(1881.24,95.89) 1(1881.24,95.89) 1(1881.24,135.75) 1(1881.24,135.75) 1(1881.24,135.89) 1(1881.24,135.89) 1(1881.24,175.75) 1(1881.24,175.75) 1(1881.24,175.89) 1(1881.24,175.89) 1(1881.24,491.89) 1(1881.24,491.89) 1(1881.24,531.89) 1(1881.24,531.89) 1(1881.24,571.89) 1(1881.24,571.89) 1(1913.24,491.89) 1(1913.24,571.89) 1(1915.24,95.89) 1(1915.24,175.89) 1(1925.15,2898.43) 1(1925.15,2898.43) 1(1925.15,2921.43) 1(1925.15,2971.43) 1(1925.15,2994.43) 1(1925.15,2994.43) 1(1928.15,2419.43) 1(1928.15,2419.43) 1(1928.15,2442.43) 1(1928.15,2492.43) 1(1928.15,2515.43) 1(1928.15,2515.43) 1(1930.89,-448.52) 1(1930.89,-448.52) 1(1930.89,-425.52) 1(1930.89,-375.52) 1(1930.89,-352.52) 1(1930.89,-352.52) 1(1951.15,2794.81) 1(1951.15,2794.81) 1(1951.15,2817.81) 1(1951.15,2867.81) 1(1951.15,2890.81) 1(1951.15,2890.81) 1(1966.15,2898.43) 1(1966.15,2898.43) 1(1966.15,2921.43) 1(1966.15,2971.43) 1(1966.15,2994.43) 1(1966.15,2994.43) 1(1969.15,2419.43) 1(1969.15,2419.43) 1(1969.15,2442.43) 1(1969.15,2492.43) 1(1969.15,2515.43) 1(1969.15,2515.43) 1(1971.89,-448.52) 1(1971.89,-448.52) 1(1971.89,-425.52) 1(1971.89,-375.52) 1(1971.89,-352.52) 1(1971.89,-352.52) 1(1974.65,708.88) 1(1974.65,708.88) 1(1974.65,897.86) 1(1974.65,897.86) 1(1974.65,744.32) 1(1974.65,862.43) 1(1980.76,-143.75) 1(1980.76,-143.75) 1(1980.76,-48.48) 1(1980.76,-48.48) 1(1992.15,2794.81) 1(1992.15,2794.81) 1(1992.15,2817.81) 1(1992.15,2867.81) 1(1992.15,2890.81) 1(1992.15,2890.81) 1(1993.24,491.89) 1(1993.24,571.89) 1(1994.89,-448.52) 1(1994.89,-448.52) 1(1994.89,-425.52) 1(1994.89,-375.52) 1(1994.89,-352.52) 1(1994.89,-352.52) 1(1995.24,95.89) 1(1995.24,175.89) 1(2016.19,-143.75) 1(2016.19,-48.48) 1(2027.24,491.89) 1(2027.24,491.89) 1(2027.24,531.89) 1(2027.24,531.89) 1(2027.24,571.89) 1(2027.24,571.89) 1(2029.24,95.89) 1(2029.24,95.89) 1(2029.24,135.89) 1(2029.24,135.89) 1(2029.24,175.89) 1(2029.24,175.89) 1(2035.89,-448.52) 1(2035.89,-448.52) 1(2035.89,-425.52) 1(2035.89,-375.52) 1(2035.89,-352.52) 1(2035.89,-352.52) 1(2043.03,2841.92) 1(2043.03,2841.92) 1(2043.03,2851.92) 1(2043.03,2851.92) 1(2043.03,2892.92) 1(2043.03,2892.92) 1(2043.03,2800.92) 1(2043.03,2800.92) 1(2063.02,-1665.07) 1(2063.02,-1665.07) 1(2063.02,-1656.08) 1(2063.02,-1517.07) 1(2063.02,-1508.07) 1(2063.02,-1508.07) 1(2064.03,2476.98) 1(2064.03,2476.98) 1(2064.03,2517.98) 1(2064.03,2517.98) 1(2064.03,2425.92) 1(2064.03,2425.92) 1(2064.03,2466.92) 1(2064.03,2466.92) 1(2064.03,2534.96) 1(2064.03,2534.96) 1(2064.03,2575.96) 1(2064.03,2575.96) 1(2064.65,2584.93) 1(2064.65,2584.93) 1(2064.65,2625.93) 1(2064.65,2625.93) 1(2065.65,2634.93) 1(2065.65,2634.93) 1(2065.65,2675.93) 1(2065.65,2675.93) 1(2066.03,2800.92) 1(2066.03,2841.92) 1(2066.03,2851.92) 1(2066.03,2892.92) 1(2069.92,862.43) 1(2069.92,708.88) 1(2069.92,708.88) 1(2069.92,897.86) 1(2069.92,897.86) 1(2069.92,717.83) 1(2087.03,2476.98) 1(2087.03,2517.98) 1(2087.03,2534.96) 1(2087.03,2575.96) 1(2087.03,2425.92) 1(2087.03,2466.92) 1(2087.65,2584.93) 1(2087.65,2625.93) 1(2088.65,2634.93) 1(2088.65,2675.93) 1(2116.03,2841.92) 1(2116.03,2851.92) 1(2116.03,2892.92) 1(2116.03,2800.92) 1(2134.3,-143.75) 1(2134.3,-48.48) 1(2137.03,2476.98) 1(2137.03,2517.98) 1(2137.03,2425.92) 1(2137.03,2466.92) 1(2137.03,2534.96) 1(2137.03,2575.96) 1(2137.65,2584.93) 1(2137.65,2625.93) 1(2138.65,2634.93) 1(2138.65,2675.93) 1(2139.03,2800.92) 1(2139.03,2800.92) 1(2139.03,2841.92) 1(2139.03,2841.92) 1(2139.03,2851.92) 1(2139.03,2851.92) 1(2139.03,2892.92) 1(2139.03,2892.92) 1(2160.03,2476.98) 1(2160.03,2476.98) 1(2160.03,2517.98) 1(2160.03,2517.98) 1(2160.03,2534.96) 1(2160.03,2534.96) 1(2160.03,2575.96) 1(2160.03,2575.96) 1(2160.03,2425.92) 1(2160.03,2425.92) 1(2160.03,2466.92) 1(2160.03,2466.92) 1(2160.65,2584.93) 1(2160.65,2584.93) 1(2160.65,2625.93) 1(2160.65,2625.93) 1(2161.65,2634.93) 1(2161.65,2634.93) 1(2161.65,2675.93) 1(2161.65,2675.93) 1(2169.73,-143.75) 1(2169.73,-143.75) 1(2169.73,-48.48) 1(2169.73,-48.48) 1(2251.39,-1440.52) 1(2251.39,-1440.52) 1(2251.39,-1406.52) 1(2251.39,-1326.52) 1(2251.39,-1292.52) 1(2251.39,-1292.52) 1(2291.39,-1440.52) 1(2291.39,-1440.52) 1(2291.39,-1292.52) 1(2291.39,-1292.52) 1(2330.02,-1665.07) 1(2330.02,-1508.07) 1(2331.39,-1440.52) 1(2331.39,-1440.52) 1(2331.39,-1406.52) 1(2331.39,-1326.52) 1(2331.39,-1292.52) 1(2331.39,-1292.52) 1(2341.39,-1440.52) 1(2341.39,-1440.52) 1(2341.39,-1406.52) 1(2341.39,-1326.52) 1(2341.39,-1292.52) 1(2341.39,-1292.52) 1(2381.39,-1440.52) 1(2381.39,-1440.52) 1(2381.39,-1292.52) 1(2381.39,-1292.52) 1(2396.94,2368.68) 1(2396.94,2368.68) 1(2396.94,2406.28) 1(2396.94,2466.28) 1(2396.94,2503.88) 1(2396.94,2503.88) 1(2405.39,2317.87) 1(2405.39,2317.87) 1(2405.39,2358.87) 1(2405.39,2358.87) 1(2421.39,-1440.52) 1(2421.39,-1440.52) 1(2421.39,-1406.52) 1(2421.39,-1326.52) 1(2421.39,-1292.52) 1(2421.39,-1292.52) 1(2421.41,1655.85) 1(2421.41,1655.85) 1(2421.41,1710.32) 1(2421.41,1710.32) 1(2428.39,2317.87) 1(2428.39,2358.87) 1(2447.39,1655.85) 1(2447.39,1710.32) 1(2458.39,2115.98) 1(2458.39,2115.98) 1(2458.39,2156.98) 1(2458.39,2156.98) 1(2468.89,1011.48) 1(2468.89,1011.48) 1(2468.89,1034.48) 1(2468.89,1084.48) 1(2468.89,1107.48) 1(2468.89,1107.48) 1(2472.44,2368.68) 1(2472.44,2368.68) 1(2472.44,2503.88) 1(2472.44,2503.88) 1(2473.14,2369.38) 1(2473.14,2369.38) 1(2473.14,2406.28) 1(2473.14,2466.28) 1(2473.14,2503.19) 1(2473.14,2503.19) 1(2477.89,743.86) 1(2477.89,743.86) 1(2477.89,766.86) 1(2477.89,816.86) 1(2477.89,839.86) 1(2477.89,839.86) 1(2478.39,2317.87) 1(2478.39,2358.87) 1(2481.39,2115.98) 1(2481.39,2156.98) 1(2491.39,2367.48) 1(2491.39,2367.48) 1(2491.39,2401.48) 1(2491.39,2481.48) 1(2491.39,2515.48) 1(2491.39,2515.48) 1(2493.45,1393.5) 1(2493.45,1393.5) 1(2493.45,1419.48) 1(2493.45,1487.48) 1(2493.45,1513.47) 1(2493.45,1513.47) 1(2501.39,2317.87) 1(2501.39,2317.87) 1(2501.39,2358.87) 1(2501.39,2358.87) 1(2509.89,1011.48) 1(2509.89,1011.48) 1(2509.89,1034.48) 1(2509.89,1084.48) 1(2509.89,1107.48) 1(2509.89,1107.48) 1(2515.39,1655.85) 1(2515.39,1710.32) 1(2518.89,743.86) 1(2518.89,743.86) 1(2518.89,766.86) 1(2518.89,816.86) 1(2518.89,839.86) 1(2518.89,839.86) 1(2531.39,2115.98) 1(2531.39,2156.98) 1(2531.39,2367.48) 1(2531.39,2367.48) 1(2531.39,2515.48) 1(2531.39,2515.48) 1(2541.38,1655.85) 1(2541.38,1655.85) 1(2541.38,1710.32) 1(2541.38,1710.32) 1(2547.91,1393.5) 1(2547.91,1393.5) 1(2547.91,1419.48) 1(2547.91,1487.48) 1(2547.91,1513.47) 1(2547.91,1513.47) 1(2554.39,2115.98) 1(2554.39,2115.98) 1(2554.39,2156.98) 1(2554.39,2156.98) 1(2571.39,2367.48) 1(2571.39,2367.48) 1(2571.39,2401.48) 1(2571.39,2481.48) 1(2571.39,2515.48) 1(2571.39,2515.48) 1(2574.22,-990.36) 1(2574.22,-990.36) 1(2574.22,-967.36) 1(2574.22,-917.36) 1(2574.22,-894.36) 1(2574.22,-894.36) 1(2584.39,2548.98) 1(2584.39,2548.98) 1(2584.39,2589.98) 1(2584.39,2589.98) 1(2589.39,2620.98) 1(2589.39,2620.98) 1(2589.39,2661.98) 1(2589.39,2661.98) 1(2607.39,2548.98) 1(2607.39,2589.98) 1(2612.39,2620.98) 1(2612.39,2661.98) 1(2612.74,1422.4) 1(2612.74,1422.4) 1(2612.74,1446.03) 1(2612.74,1721.62) 1(2612.74,1745.24) 1(2612.74,1745.24) 1(2612.74,2097.4) 1(2612.74,2097.4) 1(2612.74,2121.03) 1(2612.74,2396.62) 1(2612.74,2420.24) 1(2612.74,2420.24) 1(2615.22,-990.36) 1(2615.22,-990.36) 1(2615.22,-967.36) 1(2615.22,-917.36) 1(2615.22,-894.36) 1(2615.22,-894.36) 1(2645.89,-991.52) 1(2645.89,-991.52) 1(2645.89,-968.52) 1(2645.89,-918.52) 1(2645.89,-895.52) 1(2645.89,-895.52) 1(2657.39,2548.98) 1(2657.39,2589.98) 1(2662.39,2620.98) 1(2662.39,2661.98) 1(2675.73,1422.4) 1(2675.73,1745.24) 1(2675.73,2097.4) 1(2675.73,2420.24) 1(2680.39,2548.98) 1(2680.39,2548.98) 1(2680.39,2589.98) 1(2680.39,2589.98) 1(2685.39,2620.98) 1(2685.39,2620.98) 1(2685.39,2661.98) 1(2685.39,2661.98) 1(2686.89,-991.52) 1(2686.89,-991.52) 1(2686.89,-968.52) 1(2686.89,-918.52) 1(2686.89,-895.52) 1(2686.89,-895.52)
  round 78.74 on Mech26: 1(118.02,-1583.57) 1(159.02,3150.43) 1(2594.02,3221.43)
  round 170 on Mech26: 1(154.93,450.96) 1(158.02,3474.43) 1(2387.02,3494.43) 1(2394.93,450.96)
  round 50 on Mech26: 1(173.28,-509.78) 1(173.28,282.74) 1(643.44,868.75) 1(643.44,1661.27)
